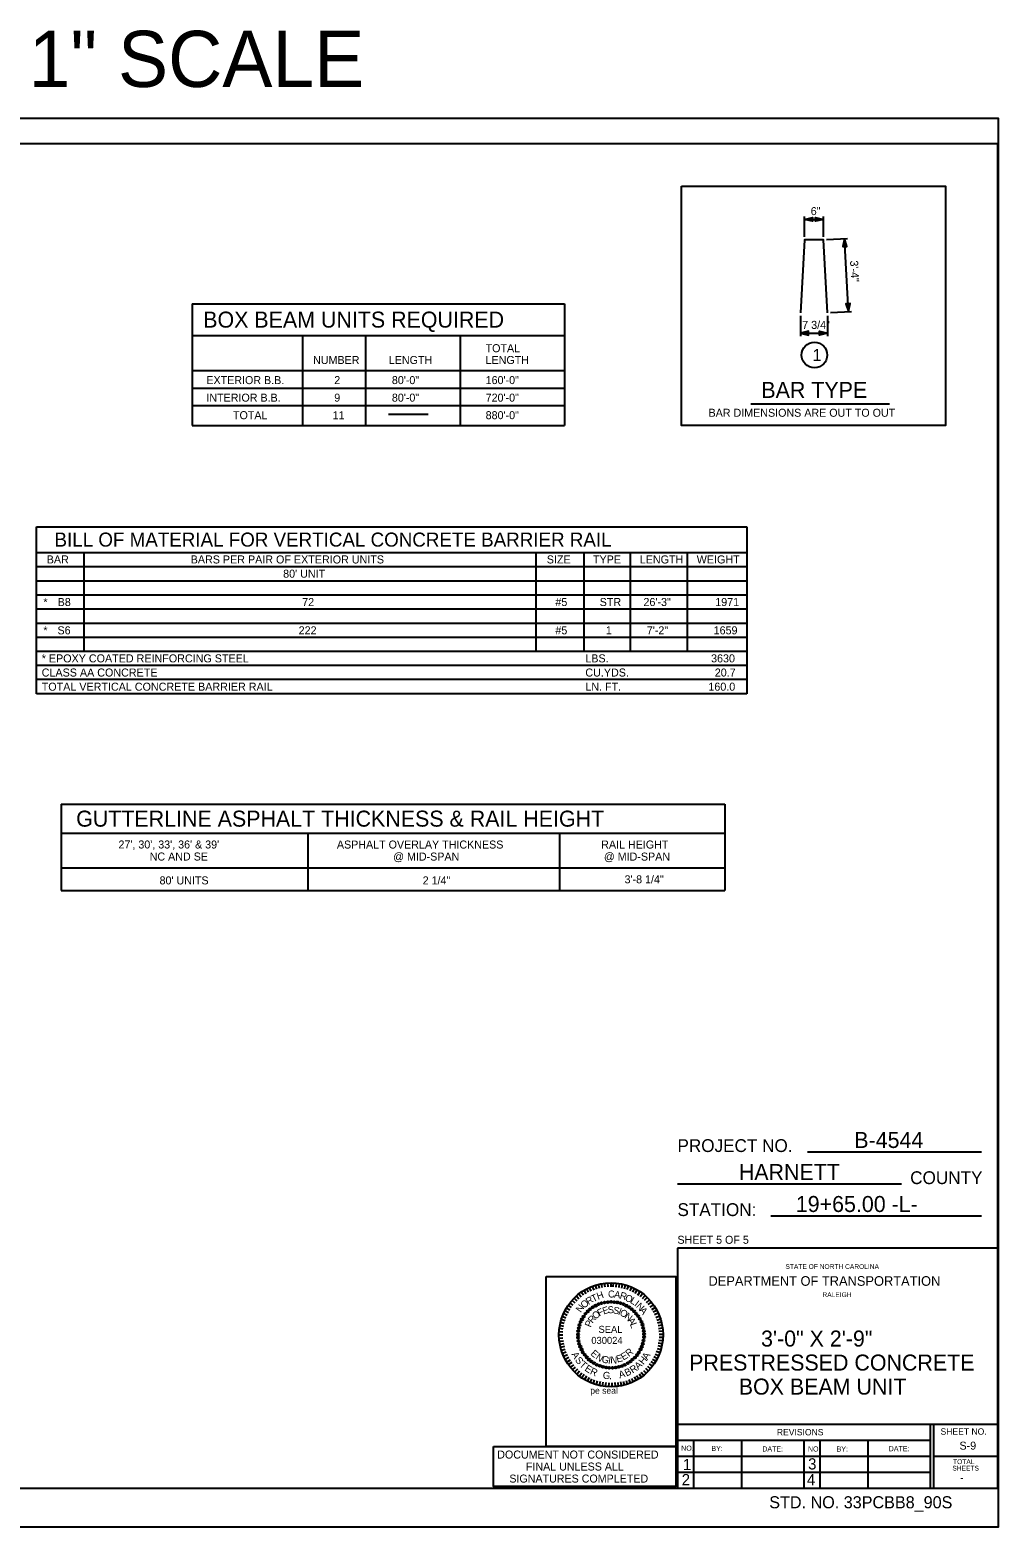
# Model space of a CAD drawing. Extents: x 0 to 217, y -54 to 96.
# Drawn here: x 135.65 to 150.77, y -53.79 to -30.41 of the extents above; entities that cross this region are included whole.
import ezdxf

# ---------------------------------------------------------------- set-up
doc = ezdxf.new("R2010")
doc.units = 0
for name, color, linetype in [('Arrowhead Terminators', 7, 'Continuous'), ('Arrowhead Terminators CELL', 7, 'Continuous'), ('Dimension Lines', 7, 'Continuous'), ('Peseal', 7, 'Continuous'), ('Plan Sheet', 7, 'Continuous'), ('Plan Sheet CELL', 7, 'Continuous'), ('Plot Shape CELL', 7, 'Continuous'), ('Rebar Lines', 7, 'Continuous'), ('Sheet Sticker Exception Certification CELL', 7, 'Continuous'), ('Subtitle Text', 7, 'Continuous'), ('Text', 7, 'Continuous'), ('Title Text', 7, 'Continuous'), ('User Information Notes', 7, 'Continuous'), ('User Information Notes CELL', 7, 'Continuous')]:
    doc.layers.add(name, color=color, linetype=linetype)

msp = doc.modelspace()

# ---------------------------------------------------------------- linework, layer by layer
at = {"layer": 'Arrowhead Terminators'}
for points in [[(147.752, -33.369), (147.877, -33.338), (147.877, -33.4)], [(148.049, -33.369), (147.924, -33.4), (147.924, -33.338)], [(147.689, -35.146), (147.814, -35.178), (147.814, -35.115)], [(148.111, -35.146), (147.986, -35.178), (147.986, -35.115)]]:
    msp.add_lwpolyline(points, close=True, dxfattribs=at)
at = {"layer": 'Arrowhead Terminators CELL'}
for points in [[(148.375, -33.669), (148.351, -33.795), (148.413, -33.792)], [(148.437, -34.809), (148.462, -34.683), (148.399, -34.686)]]:
    msp.add_lwpolyline(points, close=True, dxfattribs=at)
at = {"layer": 'Dimension Lines'}
for p, q in [((147.752, -33.641), (147.752, -33.324)), ((147.752, -33.369), (148.049, -33.369)), ((148.049, -33.641), (148.049, -33.324)), ((148.095, -33.684), (148.421, -33.666)), ((148.437, -34.809), (148.375, -33.669)), ((148.157, -34.825), (148.483, -34.807)), ((147.689, -34.875), (147.689, -35.192)), ((148.111, -34.875), (148.111, -35.192)), ((147.689, -35.146), (148.111, -35.146))]:
    msp.add_line(p, q, dxfattribs=at)
at = {"layer": 'Peseal'}
for p, q in [((144.463, -50.09), (144.439, -50.032)), ((144.506, -50.075), (144.486, -50.012)), ((144.549, -50.063), (144.533, -50)), ((144.592, -50.051), (144.58, -49.989)), ((144.635, -50.047), (144.627, -49.985)), ((144.682, -50.039), (144.678, -49.977)), ((144.728, -50.039), (144.728, -49.977)), ((144.764, -50.039), (144.768, -49.977)), ((144.807, -50.043), (144.814, -49.981)), ((144.853, -50.051), (144.861, -49.989)), ((144.896, -50.059), (144.908, -49.996)), ((144.939, -50.071), (144.955, -50.008)), ((144.982, -50.082), (145.006, -50.024)), ((144.166, -50.293), (144.119, -50.254)), ((144.197, -50.262), (144.15, -50.215)), ((144.228, -50.231), (144.189, -50.184)), ((144.264, -50.2), (144.225, -50.153)), ((144.299, -50.172), (144.264, -50.121)), ((144.338, -50.149), (144.307, -50.094)), ((144.377, -50.125), (144.35, -50.071)), ((144.416, -50.106), (144.393, -50.051)), ((145.025, -50.102), (145.053, -50.043)), ((145.068, -50.121), (145.096, -50.063)), ((145.107, -50.141), (145.139, -50.086)), ((145.146, -50.168), (145.182, -50.114)), ((145.182, -50.192), (145.221, -50.145)), ((145.221, -50.223), (145.26, -50.176)), ((145.252, -50.25), (145.295, -50.207)), ((145.283, -50.285), (145.33, -50.242)), ((144.045, -50.485), (143.986, -50.457)), ((144.064, -50.446), (144.006, -50.414)), ((144.084, -50.403), (144.029, -50.371)), ((144.111, -50.364), (144.057, -50.328)), ((144.135, -50.328), (144.088, -50.293)), ((145.311, -50.317), (145.361, -50.278)), ((145.342, -50.356), (145.393, -50.321)), ((145.365, -50.391), (145.416, -50.36)), ((145.389, -50.43), (145.443, -50.403)), ((145.408, -50.473), (145.463, -50.446)), ((145.428, -50.516), (145.486, -50.493)), ((143.982, -50.7), (143.924, -50.692)), ((143.99, -50.657), (143.928, -50.645)), ((143.998, -50.614), (143.939, -50.598)), ((144.01, -50.571), (143.951, -50.551)), ((144.025, -50.528), (143.967, -50.504)), ((145.443, -50.559), (145.502, -50.539)), ((145.455, -50.602), (145.514, -50.586)), ((145.463, -50.645), (145.525, -50.633)), ((145.471, -50.688), (145.533, -50.68)), ((145.475, -50.731), (145.537, -50.727)), ((143.978, -50.746), (143.916, -50.743)), ((143.978, -50.793), (143.916, -50.793)), ((143.978, -50.84), (143.916, -50.844)), ((143.986, -50.887), (143.924, -50.895)), ((143.99, -50.93), (143.932, -50.942)), ((145.459, -50.957), (145.521, -50.973)), ((145.467, -50.914), (145.529, -50.926)), ((145.475, -50.871), (145.537, -50.879)), ((145.478, -50.778), (145.541, -50.778)), ((145.478, -50.825), (145.541, -50.828)), ((144.002, -50.973), (143.939, -50.989)), ((144.014, -51.016), (143.955, -51.035)), ((144.029, -51.059), (143.971, -51.082)), ((144.049, -51.102), (143.99, -51.129)), ((144.068, -51.141), (144.01, -51.172)), ((144.092, -51.184), (144.037, -51.215)), ((145.377, -51.168), (145.432, -51.2)), ((145.396, -51.129), (145.455, -51.157)), ((145.416, -51.09), (145.475, -51.114)), ((145.436, -51.043), (145.494, -51.067)), ((145.447, -51), (145.51, -51.02)), ((144.115, -51.219), (144.064, -51.254)), ((144.143, -51.258), (144.092, -51.297)), ((144.17, -51.293), (144.127, -51.332)), ((144.205, -51.325), (144.158, -51.371)), ((144.236, -51.356), (144.197, -51.403)), ((144.271, -51.387), (144.236, -51.434)), ((144.307, -51.41), (144.271, -51.461)), ((144.346, -51.434), (144.314, -51.489)), ((145.127, -51.422), (145.162, -51.477)), ((145.166, -51.399), (145.201, -51.45)), ((145.201, -51.371), (145.24, -51.422)), ((145.236, -51.344), (145.275, -51.387)), ((145.268, -51.309), (145.314, -51.356)), ((145.299, -51.278), (145.346, -51.321)), ((145.326, -51.243), (145.377, -51.282)), ((145.35, -51.207), (145.404, -51.243)), ((144.385, -51.457), (144.357, -51.512)), ((144.424, -51.477), (144.4, -51.532)), ((144.467, -51.493), (144.447, -51.551)), ((144.514, -51.508), (144.494, -51.567)), ((144.557, -51.52), (144.541, -51.578)), ((144.6, -51.528), (144.588, -51.59)), ((144.646, -51.535), (144.639, -51.598)), ((144.693, -51.539), (144.689, -51.602)), ((144.74, -51.539), (144.74, -51.602)), ((144.787, -51.535), (144.791, -51.598)), ((144.834, -51.532), (144.842, -51.594)), ((144.877, -51.524), (144.889, -51.586)), ((144.92, -51.516), (144.936, -51.575)), ((144.963, -51.5), (144.982, -51.563)), ((145.006, -51.485), (145.029, -51.543)), ((145.049, -51.469), (145.076, -51.524)), ((145.088, -51.446), (145.119, -51.504))]:
    msp.add_line(p, q, dxfattribs=at)
for centre, radius in [((144.68, -50.278), 0.0157), ((144.728, -50.274), 0.0156), ((144.777, -50.278), 0.0157), ((144.826, -50.282), 0.0161), ((144.301, -50.502), 0.0168), ((144.328, -50.459), 0.0138), ((144.365, -50.422), 0.0166), ((144.402, -50.389), 0.0168), ((144.445, -50.358), 0.0168), ((144.49, -50.332), 0.0175), ((144.535, -50.311), 0.0149), ((144.58, -50.295), 0.0142), ((144.629, -50.284), 0.0138), ((144.877, -50.295), 0.0142), ((144.922, -50.311), 0.0149), ((144.967, -50.334), 0.0157), ((145.01, -50.358), 0.0157), ((145.051, -50.387), 0.0153), ((145.09, -50.422), 0.0153), ((145.123, -50.459), 0.0153), ((145.152, -50.496), 0.0157), ((144.217, -50.733), 0.0157), ((144.225, -50.684), 0.0161), ((144.236, -50.635), 0.0167), ((144.254, -50.588), 0.0149), ((144.277, -50.547), 0.018), ((145.18, -50.539), 0.0157), ((145.203, -50.584), 0.0149), ((145.221, -50.631), 0.0167), ((145.232, -50.68), 0.0161), ((145.24, -50.729), 0.0157), ((144.213, -50.782), 0.0156), ((144.213, -50.83), 0.0157), ((144.221, -50.881), 0.0157), ((144.232, -50.93), 0.0161), ((144.248, -50.975), 0.0167), ((145.209, -50.975), 0.0167), ((145.225, -50.926), 0.0161), ((145.236, -50.877), 0.0157), ((145.244, -50.778), 0.0156), ((145.244, -50.826), 0.0157), ((144.268, -51.02), 0.0175), ((144.289, -51.063), 0.0157), ((144.318, -51.1), 0.0153), ((144.35, -51.141), 0.0166), ((144.385, -51.176), 0.0166), ((144.422, -51.205), 0.0168), ((145.031, -51.207), 0.0153), ((145.066, -51.176), 0.0153), ((145.103, -51.143), 0.0153), ((145.137, -51.104), 0.0168), ((145.164, -51.063), 0.0157), ((145.191, -51.016), 0.0157), ((144.463, -51.233), 0.0157), ((144.508, -51.256), 0.0149), ((144.555, -51.274), 0.0167), ((144.603, -51.289), 0.0161), ((144.652, -51.301), 0.0157), ((144.701, -51.305), 0.0156), ((144.752, -51.305), 0.0156), ((144.801, -51.301), 0.0157), ((144.85, -51.289), 0.0161), ((144.898, -51.276), 0.0149), ((144.943, -51.258), 0.0175), ((144.99, -51.233), 0.0157)]:
    msp.add_circle(centre, radius, dxfattribs=at)
at = {"layer": 'Plan Sheet'}
for p, q in [((138.184, -34.688), (144.002, -34.688)), ((138.184, -34.688), (138.184, -36.591)), ((144.002, -34.688), (144.002, -36.591)), ((138.184, -35.182), (144.002, -35.182)), ((139.909, -35.182), (139.909, -36.591)), ((140.893, -35.182), (140.893, -36.591)), ((142.374, -35.182), (142.374, -36.591)), ((138.184, -35.73), (144.002, -35.73)), ((138.184, -36.004), (144.002, -36.004)), ((138.184, -36.278), (144.002, -36.278)), ((138.184, -36.591), (144.002, -36.591)), ((135.756, -40.778), (135.756, -38.171)), ((135.756, -38.171), (146.851, -38.171)), ((146.851, -38.171), (146.851, -40.778)), ((135.756, -38.57), (146.851, -38.57)), ((136.493, -38.57), (136.493, -40.115)), ((143.555, -38.57), (143.555, -40.115)), ((144.303, -38.57), (144.303, -40.115)), ((145.027, -38.57), (145.027, -40.115)), ((145.918, -38.57), (145.918, -40.115)), ((135.756, -38.791), (146.851, -38.791)), ((135.756, -39.012), (146.851, -39.012)), ((135.756, -39.233), (146.851, -39.233)), ((135.756, -39.453), (146.851, -39.453)), ((135.756, -39.674), (146.851, -39.674)), ((135.756, -39.895), (146.851, -39.895)), ((135.756, -40.115), (143.549, -40.115)), ((135.756, -40.115), (146.851, -40.115)), ((146.851, -40.336), (135.756, -40.336)), ((146.851, -40.557), (135.756, -40.557)), ((146.851, -40.778), (135.756, -40.778)), ((136.14, -42.5), (146.508, -42.5)), ((136.14, -42.5), (136.14, -43.848)), ((146.508, -42.5), (146.508, -43.848)), ((136.14, -42.955), (146.508, -42.955)), ((139.994, -42.955), (139.994, -43.848)), ((143.926, -42.955), (143.926, -43.848)), ((136.14, -43.498), (146.508, -43.498)), ((136.14, -43.498), (146.508, -43.498)), ((136.14, -43.848), (146.508, -43.848)), ((136.14, -43.848), (146.508, -43.848))]:
    msp.add_line(p, q, dxfattribs=at)
msp.add_lwpolyline([(145.831, -32.852), (149.952, -32.852), (149.952, -36.591), (145.831, -36.591)], close=True, dxfattribs=at)
at = {"layer": 'Plan Sheet CELL'}
for p, q in [((150.775, -31.791), (150.775, -31.791)), ((118.765, -32.185), (150.766, -32.185)), ((150.766, -32.185), (150.766, -53.185)), ((150.516, -47.934), (147.799, -47.934)), ((149.266, -48.435), (145.766, -48.435)), ((150.516, -48.934), (147.226, -48.934)), ((150.766, -49.434), (145.766, -49.434)), ((145.766, -49.434), (145.766, -53.185)), ((145.766, -52.184), (150.766, -52.184)), ((149.716, -52.184), (149.716, -53.185)), ((149.766, -52.184), (149.766, -53.185)), ((145.766, -52.434), (149.718, -52.434)), ((145.769, -52.434), (145.769, -53.185)), ((146.016, -52.434), (146.016, -53.185)), ((146.766, -52.438), (146.766, -53.188)), ((147.742, -52.434), (147.742, -53.191)), ((147.992, -52.434), (147.992, -53.185)), ((148.742, -52.434), (148.742, -53.185)), ((145.766, -52.685), (149.726, -52.685)), ((149.766, -52.685), (150.757, -52.685)), ((145.766, -52.934), (149.718, -52.934)), ((118.765, -53.185), (150.766, -53.185)), ((150.775, -53.791), (150.775, -53.791))]:
    msp.add_line(p, q, dxfattribs=at)
at = {"layer": 'Plot Shape CELL'}
msp.add_lwpolyline([(117.711, -31.791), (150.775, -31.791), (150.775, -53.791), (117.711, -53.791)], close=True, dxfattribs=at)
at = {"layer": 'Rebar Lines'}
msp.add_lwpolyline([(148.111, -34.829), (148.049, -33.687), (147.752, -33.687), (147.689, -34.829)], dxfattribs=at)
at = {"layer": 'Sheet Sticker Exception Certification CELL'}
msp.add_lwpolyline([(142.892, -52.533), (145.741, -52.533), (145.741, -53.16), (142.892, -53.16)], close=True, dxfattribs=at)
at = {"layer": 'Text'}
msp.add_line((141.25, -36.412), (141.874, -36.412), dxfattribs=at)
msp.add_circle((147.906, -35.488), 0.2, dxfattribs=at)
at = {"layer": 'Title Text'}
msp.add_line((146.91, -36.251), (149.076, -36.251), dxfattribs=at)
at = {"layer": 'User Information Notes'}
msp.add_line((144.728, -50.789), (144.728, -50.789), dxfattribs=at)
at = {"layer": 'User Information Notes CELL'}
msp.add_line((144.728, -50.789), (144.728, -50.789), dxfattribs=at)
msp.add_lwpolyline([(143.716, -49.877), (145.741, -49.877), (145.741, -52.533), (143.716, -52.533)], close=True, dxfattribs=at)
msp.add_circle((144.728, -50.789), 0.813, dxfattribs=at)

# ---------------------------------------------------------------- texts
at = {"layer": 'Peseal'}
for s, height, rotation, p in [('O', 0.109, 39.9967, (144.307, -50.383)), ('R', 0.109, 32.9699, (144.377, -50.325)), ('T', 0.109, 25.943, (144.451, -50.282)), ('H', 0.109, 18.9162, (144.525, -50.242)), ('C', 0.109, 4.8625, (144.686, -50.211)), ('A', 0.109, 350.8088, (144.771, -50.207)), ('R', 0.109, 343.7819, (144.857, -50.219)), ('O', 0.109, 336.7551, (144.936, -50.25)), ('L', 0.109, 329.7282, (145.018, -50.285)), ('I', 0.109, 322.7014, (145.084, -50.328)), ('N', 0.109, 54.0504, (144.256, -50.45)), ('R', 0.109, 50.5765, (144.439, -50.618)), ('O', 0.109, 42.5436, (144.49, -50.555)), ('F', 0.109, 26.4777, (144.545, -50.504)), ('E', 0.109, 18.4448, (144.615, -50.473)), ('S', 0.109, 2.3789, (144.678, -50.453)), ('S', 0.109, 346.313, (144.752, -50.45)), ('I', 0.109, 338.28, (144.83, -50.469)), ('O', 0.109, 330.2471, (144.853, -50.473)), ('N', 0.109, 322.2141, (144.928, -50.52)), ('N', 0.109, 315.6745, (145.111, -50.352)), ('A', 0.109, 308.6477, (145.166, -50.41)), ('P', 0.109, 66.6424, (144.412, -50.68)), ('A', 0.109, 306.1483, (144.982, -50.567)), ('L', 0.109, 290.0824, (145.021, -50.621)), ('A', 0.111, 300.3993, (144.104, -51.093)), ('S', 0.111, 309.4349, (144.159, -51.187)), ('T', 0.111, 318.1096, (144.226, -51.268)), ('E', 0.109, 318.5179, (144.4, -51.094)), ('N', 0.109, 326.5361, (144.478, -51.16)), ('G', 0.109, 342.5725, (144.572, -51.211)), ('I', 0.109, 350.5906, (144.678, -51.235)), ('N', 0.109, 358.6088, (144.717, -51.235)), ('E', 0.109, 14.6452, (144.826, -51.223)), ('E', 0.109, 30.6815, (144.92, -51.192)), ('R', 0.109, 38.6997, (145.006, -51.137)), ('H', 0.111, 51.3597, (145.235, -51.264)), ('A', 0.111, 59.6007, (145.298, -51.187)), ('E', 0.111, 327.1453, (144.307, -51.341)), ('R', 0.111, 335.458, (144.391, -51.396)), ('G', 0.111, 353.3858, (144.595, -51.471)), ('A', 0.111, 15.7955, (144.864, -51.47)), ('B', 0.111, 24.8312, (144.97, -51.441)), ('R', 0.111, 33.5776, (145.066, -51.396)), ('A', 0.111, 42.3241, (145.154, -51.338)), ('.', 0.111, 2.1323, (144.7, -51.483))]:
    msp.add_text(s, height=height, rotation=rotation, dxfattribs=at).set_placement(p)
for s, p in [('SEAL', (144.533, -50.758)), ('030024', (144.421, -50.93))]:
    msp.add_text(s, height=0.1094, dxfattribs=at).set_placement(p)
at = {"layer": 'Plan Sheet CELL'}
for s, height, p in [('PROJECT NO.', 0.2, (145.766, -47.934)), ('COUNTY', 0.2, (149.402, -48.435)), ('STATION:', 0.2, (145.766, -48.934)), ('SHEET 5 OF 5', 0.125, (145.766, -49.367)), ('STATE OF NORTH CAROLINA', 0.07499, (147.453, -49.76)), ('DEPARTMENT OF TRANSPORTATION', 0.14999, (146.251, -50.023)), ('RALEIGH', 0.075, (148.031, -50.199)), ('REVISIONS', 0.1, (147.319, -52.359)), ('SHEET NO.', 0.1, (149.876, -52.349)), ('NO.', 0.0797, (145.825, -52.599)), ('BY:', 0.0797, (146.297, -52.603)), ('DATE:', 0.0797, (147.092, -52.611)), ('NO.', 0.0797, (147.805, -52.611)), ('BY:', 0.0797, (148.252, -52.612)), ('DATE:', 0.0797, (149.067, -52.607)), ('1', 0.175, (145.852, -52.901)), ('3', 0.175, (147.807, -52.892)), ('SHEETS', 0.075, (150.061, -52.909)), ('TOTAL', 0.075, (150.072, -52.808)), ('2', 0.175, (145.833, -53.138)), ('4', 0.175, (147.789, -53.138))]:
    msp.add_text(s, height=height, dxfattribs=at).set_placement(p)
at = {"layer": 'Sheet Sticker Exception Certification CELL'}
for s, p in [('DOCUMENT NOT CONSIDERED', (142.951, -52.721)), ('FINAL UNLESS ALL', (143.399, -52.908)), ('SIGNATURES COMPLETED', (143.14, -53.096))]:
    msp.add_text(s, height=0.12472, dxfattribs=at).set_placement(p)
at = {"layer": 'Subtitle Text'}
for s, height, p in [('BOX BEAM UNITS REQUIRED', 0.25, (138.358, -35.06)), ('3\'-0" X 2\'-9"', 0.25, (147.072, -50.972)), ('PRESTRESSED CONCRETE', 0.25, (145.948, -51.347)), ('BOX BEAM UNIT', 0.25, (146.724, -51.722)), ('STD. NO. 33PCBB8_90S', 0.18869, (147.2, -53.498))]:
    msp.add_text(s, height=height, dxfattribs=at).set_placement(p)
at = {"layer": 'Text'}
for s, rotation, p in [('6"', 360, (147.848, -33.303)), ('3\'-4"', 273.139, (148.462, -34.015)), ('7 3/4"', 360, (147.715, -35.08))]:
    msp.add_text(s, height=0.1255, rotation=rotation, dxfattribs=at).set_placement(p)
for s, height, p in [('NUMBER', 0.125, (140.074, -35.628)), ('LENGTH', 0.125, (141.257, -35.628)), ('TOTAL', 0.125, (142.769, -35.444)), ('LENGTH', 0.125, (142.769, -35.628)), ('1', 0.188, (147.876, -35.582)), ('EXTERIOR B.B.', 0.125, (138.407, -35.942)), ('2', 0.125, (140.405, -35.942)), ('80\'-0"', 0.125, (141.305, -35.942)), ('160\'-0"', 0.125, (142.77, -35.942)), ('INTERIOR B.B.', 0.125, (138.407, -36.216)), ('9', 0.125, (140.405, -36.216)), ('80\'-0"', 0.125, (141.305, -36.216)), ('720\'-0"', 0.125, (142.77, -36.216)), ('TOTAL', 0.125, (138.823, -36.49)), ('11', 0.125, (140.38, -36.49)), ('880\'-0"', 0.125, (142.77, -36.49)), ('BAR DIMENSIONS ARE OUT TO OUT', 0.125, (146.252, -36.452)), ('BILL OF MATERIAL FOR VERTICAL CONCRETE BARRIER RAIL', 0.2193, (136.035, -38.48)), ('BAR', 0.1255, (135.913, -38.743)), ('BARS PER PAIR OF EXTERIOR UNITS', 0.12546, (138.162, -38.743)), ('SIZE', 0.1255, (143.725, -38.743)), ('TYPE', 0.1255, (144.446, -38.743)), ('LENGTH', 0.1255, (145.177, -38.743)), ('WEIGHT', 0.1255, (146.067, -38.743)), ("80' UNIT", 0.1255, (139.606, -38.965)), ('*', 0.125, (135.861, -39.41)), ('B8', 0.1255, (136.084, -39.408)), ('72', 0.1255, (139.904, -39.408)), ('#5', 0.1255, (143.859, -39.408)), ('STR', 0.1255, (144.551, -39.408)), ('26\'-3"', 0.1255, (145.235, -39.408)), ('1971', 0.1255, (146.356, -39.408)), ('*', 0.125, (135.861, -39.851)), ('S6', 0.1255, (136.081, -39.85)), ('222', 0.1255, (139.848, -39.85)), ('#5', 0.1255, (143.859, -39.85)), ('1', 0.125, (144.647, -39.85)), ('7\'-2"', 0.1255, (145.287, -39.85)), ('1659', 0.1255, (146.331, -39.85)), ('* EPOXY COATED REINFORCING STEEL', 0.12546, (135.835, -40.288)), ('LBS. ', 0.1255, (144.327, -40.288)), ('3630', 0.1255, (146.291, -40.288)), ('CLASS AA CONCRETE', 0.12546, (135.835, -40.509)), ('CU.YDS.', 0.1255, (144.327, -40.509)), ('20.7', 0.1255, (146.349, -40.509)), ('TOTAL VERTICAL CONCRETE BARRIER RAIL', 0.12546, (135.835, -40.73)), ('LN. FT.', 0.1255, (144.327, -40.73)), ('160.0', 0.1255, (146.249, -40.73)), ('GUTTERLINE ASPHALT THICKNESS & RAIL HEIGHT', 0.25, (136.373, -42.853)), ('ASPHALT OVERLAY THICKNESS', 0.125, (140.446, -43.195)), ('@ MID-SPAN', 0.125, (141.325, -43.383)), ('RAIL HEIGHT', 0.125, (144.575, -43.195)), ('@ MID-SPAN', 0.125, (144.617, -43.383)), ("80' UNITS", 0.125, (137.676, -43.755)), ('2 1/4"', 0.125, (141.786, -43.755)), ('3\'-8 1/4"', 0.125, (144.94, -43.738)), ('S-9', 0.125, (150.172, -52.582)), ('-', 0.125, (150.181, -53.082))]:
    msp.add_text(s, height=height, dxfattribs=at).set_placement(p)
at = {"layer": 'Title Text'}
for s, p in [('BAR TYPE', (147.077, -36.158)), ('B-4544', (148.529, -47.871)), ('HARNETT', (146.725, -48.372)), ('19+65.00 -L-', (147.615, -48.871))]:
    msp.add_text(s, height=0.25, dxfattribs=at).set_placement(p)
at = {"layer": 'User Information Notes'}
for s, height, p in [('1" SCALE', 0.8772, (135.632, -31.302)), ("27', 30', 33', 36' & 39' ", 0.125, (137.034, -43.194)), ('   NC AND SE', 0.125, (137.382, -43.382))]:
    msp.add_text(s, height=height, dxfattribs=at).set_placement(p)
at = {"layer": 'User Information Notes CELL'}
msp.add_text('pe seal', height=0.1, dxfattribs=at).set_placement((144.404, -51.709))

doc.saveas('drawing.dxf')
